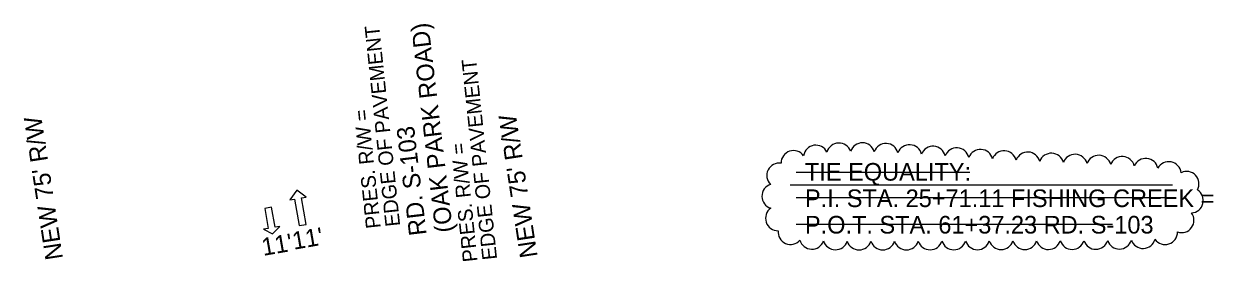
# Model space of a CAD drawing. Extents: x 1964377 to 1966966, y 1116414 to 1123213.
# Drawn here: x 1965885.5 to 1966291, y 1121526.1 to 1121606.9 of the extents above; entities that cross this region are included whole.
import ezdxf

# ---------------------------------------------------------------- set-up
doc = ezdxf.new("R2010")
doc.units = 0
for name, color, linetype in [('RD_EX_RW_TX', 7, 'Continuous'), ('RD_HC_Data', 7, 'Continuous'), ('RD_PD_Final_LnLine', 7, 'Continuous'), ('RD_PD_Final_TX', 7, 'Continuous'), ('RD_PD_RW_TX', 7, 'Continuous'), ('RD_TX_RoadID', 7, 'Continuous')]:
    doc.layers.add(name, color=color, linetype=linetype)

msp = doc.modelspace()

# ---------------------------------------------------------------- linework, layer by layer
at = {"layer": 'RD_HC_Data'}
for p, q in [((1966148.84, 1121556.44), (1966208.07, 1121556.44)), ((1966277.06, 1121552.05), (1966146.8, 1121552.05)), ((1966148.84, 1121547.86), (1966276.38, 1121547.86)), ((1966148.84, 1121538.76), (1966256.7, 1121538.76))]:
    msp.add_line(p, q, dxfattribs=at)
for centre, start, end in [((1966163.39, 1121562.12), 19.5939, 164.5939), ((1966171.39, 1121562.2), 16.5605, 161.5605), ((1966179.42, 1121561.96), 15.0154, 160.0154), ((1966147.9, 1121559.55), 36.0033, 181.0033), ((1966155.51, 1121561.38), 26.0622, 171.0622), ((1966187.46, 1121561.54), 14.0369, 159.0369), ((1966195.5, 1121561.02), 13.515, 158.515), ((1966203.56, 1121560.47), 13.7388, 158.7388), ((1966211.62, 1121559.96), 14.0153, 159.0153), ((1966219.68, 1121559.49), 14.279, 159.279), ((1966227.75, 1121559.05), 14.5307, 159.5307), ((1966235.81, 1121558.65), 14.7713, 159.7713), ((1966243.88, 1121558.28), 15.0017, 160.0017), ((1966251.95, 1121557.94), 15.1442, 160.1442), ((1966143.02, 1121555.3), 81.1057, 226.1057), ((1966259.98, 1121557.53), 14.0483, 159.0483), ((1966267.98, 1121556.89), 11.7522, 156.7522), ((1966275.85, 1121555.75), 6.7981, 151.7981), ((1966281.9, 1121552.45), 330.929, 115.929), ((1966141.38, 1121548.22), 107.7686, 252.7686), ((1966283.37, 1121546.8), 273.196, 58.196), ((1966142.61, 1121540.75), 125.9776, 270.9776), ((1966280.19, 1121540.08), 251.0926, 36.0926), ((1966146.89, 1121536.08), 174.0222, 319.0222), ((1966267.06, 1121534.71), 199.6548, 344.6548), ((1966274.58, 1121536.04), 215.4674, 0.4674), ((1966154.16, 1121534.44), 195.4456, 340.4456), ((1966162.2, 1121534.26), 196.9899, 341.9899), ((1966170.26, 1121534.21), 197.363, 342.363), ((1966178.33, 1121534.21), 197.5497, 342.5497), ((1966186.39, 1121534.22), 197.652, 342.652), ((1966194.47, 1121534.24), 197.6571, 342.6571), ((1966202.54, 1121534.26), 197.6522, 342.6522), ((1966210.61, 1121534.28), 197.6477, 342.6477), ((1966218.68, 1121534.31), 197.6436, 342.6436), ((1966226.75, 1121534.33), 197.6399, 342.6399), ((1966234.82, 1121534.35), 197.6465, 342.6465), ((1966242.89, 1121534.37), 197.7467, 342.7467), ((1966250.96, 1121534.42), 197.9249, 342.9249), ((1966259.02, 1121534.5), 198.2615, 343.2615)]:
    msp.add_arc(centre, 4.23, start, end, dxfattribs=at)
at = {"layer": 'RD_PD_Final_LnLine'}
for points in [[(1965979.37, 1121538.24), (1965981.73, 1121538.64), (1965980.21, 1121547.69), (1965981.81, 1121547.96), (1965978.55, 1121550.28), (1965976.24, 1121547.02), (1965977.84, 1121547.29)], [(1965970.01, 1121544.48), (1965967.65, 1121544.08), (1965968.79, 1121537.29), (1965967.19, 1121537.02), (1965970.33, 1121535.4), (1965972.76, 1121537.96), (1965971.16, 1121537.69)], [(1965970.01, 1121544.48), (1965967.65, 1121544.08), (1965968.79, 1121537.29), (1965967.19, 1121537.02), (1965970.33, 1121535.4), (1965972.76, 1121537.96), (1965971.16, 1121537.69)]]:
    msp.add_lwpolyline(points, close=True, dxfattribs=at)

# ---------------------------------------------------------------- texts
at = {"layer": 'RD_EX_RW_TX'}
for s, p in [('EDGE OF PAVEMENT', (1966013.84, 1121538.19)), ('EDGE OF PAVEMENT', (1966046.88, 1121526.82)), ('PRES. R/W = ', (1966007.21, 1121537.5)), ('PRES. R/W = ', (1966040.25, 1121526.12))]:
    msp.add_text(s, height=5, rotation=95.997, dxfattribs=at).set_placement(p)
at = {"layer": 'RD_HC_Data'}
for s, p in [('TIE EQUALITY:', (1966151.8, 1121553.55)), ('P.I. STA. 25+71.11 FISHING CREEK =', (1966151.8, 1121544.55)), ('P.O.T. STA. 61+37.23 RD. S-103', (1966151.8, 1121535.55))]:
    msp.add_text(s, height=6, dxfattribs=at).set_placement(p)
at = {"layer": 'RD_PD_Final_TX'}
for p in [(1965977.57, 1121530.03), (1965967.16, 1121527.94)]:
    msp.add_text("11'", height=6, rotation=9.6819, dxfattribs=at).set_placement(p)
at = {"layer": 'RD_PD_RW_TX'}
for p in [(1965898.91, 1121527.05), (1966060.7, 1121527.75)]:
    msp.add_text("NEW 75' R/W", height=6, rotation=98.7152, dxfattribs=at).set_placement(p)
at = {"layer": 'RD_TX_RoadID'}
for s, p in [('(OAK PARK ROAD)', (1966031.83, 1121536.23)), ('RD. S-103', (1966022.89, 1121535.18))]:
    msp.add_text(s, height=6, rotation=96.7215, dxfattribs=at).set_placement(p)

doc.saveas('drawing.dxf')
